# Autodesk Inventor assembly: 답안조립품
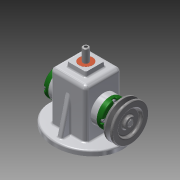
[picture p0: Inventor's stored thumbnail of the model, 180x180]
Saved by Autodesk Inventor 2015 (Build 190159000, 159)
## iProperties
Created: 2017-07
Part Number: 답안조립품
Document SubType Name: Assembly
Designer: C12
Author: C12
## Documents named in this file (16)
- C:\Users\C12\Desktop\470707V1015\답안조립품.iam
- C:\Users\C12\Desktop\470707V1015\본체.ipt
- C:\Users\C12\Desktop\470707V1015\뒤커버.ipt
- C:\Users\C12\Desktop\470707V1015\앞커버.ipt
- C:\Users\C12\Desktop\470707V1015\오일실 12 25 7.ipt
- C:\Users\C12\Desktop\470707V1015\볼트 M4 x 12.ipt
- C:\Users\C12\Desktop\470707V1015\베어링 12 x 32 x 10.ipt
- C:\Users\C12\Desktop\470707V1015\편심축.ipt
- C:\Users\C12\Desktop\470707V1015\링크.ipt
- C:\Users\C12\Desktop\470707V1015\부시.ipt
- C:\Users\C12\Desktop\470707V1015\슬라이드.ipt
- C:\Users\C12\Desktop\470707V1015\핀 5 x 18.ipt
- C:\Users\C12\Desktop\470707V1015\고정핀 1.2 x  8.ipt
- C:\Users\C12\Desktop\470707V1015\키 4 x 4 x 10.ipt
- C:\Users\C12\Desktop\470707V1015\V벨트풀리.ipt
- C:\Users\C12\Desktop\470707V1015\멈춤나사 M3x8.ipt
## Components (3 placed, 3 different names)
1. 핀 5 x 18:1
2. 고정핀 1.2 x  8:1
3. V벨트풀리:1
